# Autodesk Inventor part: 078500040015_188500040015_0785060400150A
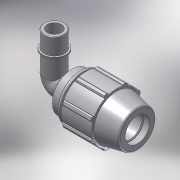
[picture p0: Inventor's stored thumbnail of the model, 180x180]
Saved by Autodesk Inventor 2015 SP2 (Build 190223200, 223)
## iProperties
Created: 2017-02
Part Number: 078500040015_188500040015_0785060400150A
Material: PVC-Piping
Description: PLASSON 90° ELBOW MALE ADAPTOR 40-1.1/2"
Document SubType Name: Modeling
Designer: KIM
Mass: 92.6774 g
Surface Area: 199.44 cm^2
Volume: 66.1981 cm^3
Density: 1.4 g/cm^3
Appearance: Smooth - White
Author: KIM
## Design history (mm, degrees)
derived "07850.ipt"
feature "Solid1::07850.ipt"
tag "TaggingFeature1"
body "Solid1"
other parameters: "d4" = 10.33333, "d5" = 31, "d7" = 82, "d9" = 17.71429, "d11" = 4.13333, "d13" = 120 deg, "d14" = 56, "d15" = 12 deg, "d16" = 71.34, "d18" = 2, "d19" = 35 deg, "d20" = 17.5 deg, "d21" = 76.26, "d23" = 0, "d25" = 360 deg, "d27" = 1.64, "d33" = 0.8, "d42" = 45.88, "d43" = 2.46, "d46" = 1.2, "d51" = 124, "d68" = 4.13333, "d72" = 66, "d73" = 47.803, "d74" = 22, "d75" = 54.97345, "d76" = 33.4621, "d77" = 24.2, "d79" = 19.1212, "d80" = 1.43409, "d83" = 0, "d84" = 0, "d91" = 61.5, "d93" = 84, "d94" = 47.803, "d95" = 33.4621, "d96" = 12.4, "d97" = 50 deg, "E_" = 82, "A_" = 124, "l_" = 84, "l_2" = 22, "A_1" = 66, "R_" = 47.803
